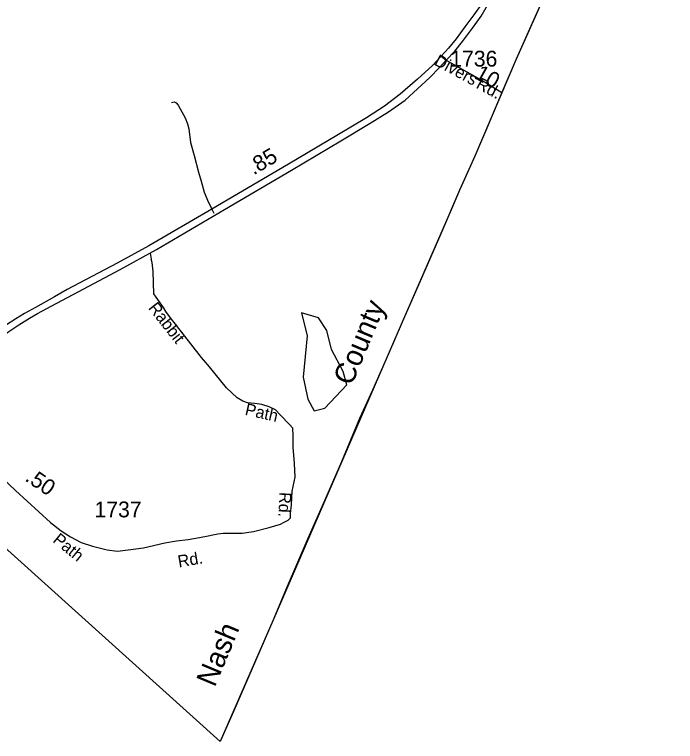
# Model space of a CAD drawing. Extents: x 2220236 to 2384410, y 720751 to 894131.
# Drawn here: x 2340787 to 2346007, y 761777 to 767520 of the extents above; entities that cross this region are included whole.
import ezdxf

# ---------------------------------------------------------------- set-up
doc = ezdxf.new("R2010")
doc.units = 0
for name, color, linetype in [('Exist Boundary Political CountyLine', 7, 'Continuous'), ('Exist Boundary Political CountyLine Label', 7, 'Continuous'), ('Exist Hydrographic Pond Under 1500 Sq Ft', 7, 'Continuous'), ('Exist Railroad Mainline', 7, 'Continuous'), ('Exist Road Non-System Type 51', 7, 'Continuous'), ('Exist Road Non-System Type 51 Label', 7, 'Continuous'), ('Exist Road Primary US Divided Attributed', 7, 'Continuous'), ('Exist Road Primary US Mileage Hundredths English Label', 7, 'Continuous'), ('Exist Road Secondary Mileage Hundredths English Label', 7, 'Continuous'), ('Exist Road Secondary Type 20 Attributed', 7, 'Continuous'), ('Exist Road Secondary Type 51 Attributed', 7, 'Continuous'), ('Exist Road Secondary Type 51 Label', 7, 'Continuous'), ('Exist Road Secondary Type 51 Number Label', 7, 'Continuous')]:
    doc.layers.add(name, color=color, linetype=linetype)

msp = doc.modelspace()

# ---------------------------------------------------------------- linework, layer by layer
at = {"layer": 'Exist Boundary Political CountyLine'}
for points in [[(2344994.6, 767717), (2344864.5, 767429.1), (2344748.7, 767168.8), (2344635.7, 766903.7), (2344523.7, 766639.6), (2344422.1, 766401.1), (2344300.6, 766131.3), (2344153.4, 765788.3), (2343991.1, 765414.9), (2343847.7, 765089), (2343739.5, 764840.1), (2343615.1, 764552.2), (2343512.5, 764327.9), (2343369.2, 763986.8), (2343235.3, 763678.1), (2343104.3, 763379.7), (2342940, 763002.5), (2342827, 762729.8), (2342662.8, 762354.6), (2342515.6, 762013.5), (2342412.1, 761776.9)], [(2342412.1, 761776.9), (2339905.1, 764034.3), (2333719, 766093.2), (2333476.1, 765987.5), (2333096.9, 765807.6)]]:
    msp.add_lwpolyline(points, dxfattribs=at)
at = {"layer": 'Exist Hydrographic Pond Under 1500 Sq Ft'}
msp.add_lwpolyline([(2343154.3, 764389.5), (2343237.4, 764409.3), (2343410.4, 764593.6), (2343383.4, 764700.8), (2343290.5, 764874.2), (2343254.4, 765023.8), (2343187.3, 765122.7), (2343053.4, 765163.2), (2343097.3, 764981.2), (2343067.4, 764655.1), (2343103.5, 764482.6), (2343154.3, 764389.5)], dxfattribs=at)
at = {"layer": 'Exist Railroad Mainline'}
msp.add_lwpolyline([(2344994.6, 767717), (2344873.7, 767449.4), (2344869.4, 767439.8), (2344860.6, 767420.2), (2344839.5, 767372.8), (2344748.7, 767168.8), (2344422.1, 766401.1), (2344316.5, 766166.7), (2344300.6, 766131.3), (2344299.8, 766129.4), (2344299.7, 766129.1), (2344299.3, 766128.2), (2344295.1, 766118.5), (2344234.1, 765976.1), (2343847.7, 765089), (2342827, 762729.8), (2342412.1, 761776.9)], dxfattribs=at)
at = {"layer": 'Exist Road Non-System Type 51'}
for p, q in [((2342311.2, 766053.2), (2342340.6, 765992)), ((2342340.6, 765992), (2342360.2, 765951.3)), ((2341857.8, 765636.1), (2341865.7, 765586.3))]:
    msp.add_line(p, q, dxfattribs=at)
for points in [[(2342027.2, 766824.8), (2342048.2, 766830), (2342063.9, 766821.3), (2342077.9, 766803.8), (2342093.6, 766774.1), (2342133.8, 766704.1), (2342153, 766656.9), (2342163.5, 766616.7), (2342177.5, 766510.1), (2342205.4, 766405.2), (2342240.4, 766274.1), (2342261.3, 766202.4), (2342284, 766116.8), (2342305, 766066.1), (2342311.2, 766053.2)], [(2341974.3, 763346.6), (2342067.1, 763363.1), (2342156.9, 763373.5), (2342246.7, 763389.2), (2342316.3, 763401.4), (2342353.4, 763408.8), (2342392.4, 763416.2), (2342435, 763421.8), (2342485.1, 763423.6), (2342583.3, 763423.6), (2342674.2, 763434.8), (2342798.4, 763468.2), (2342887.4, 763494.1), (2342917.1, 763509), (2342948.6, 763525.7), (2342965.3, 763544.2), (2342967.2, 763577.6), (2342974.6, 763646.3), (2342980.1, 763753.9), (2343002.4, 763865.2), (2342998.7, 763972.8), (2342987.6, 764100.8), (2342987.6, 764193.6), (2342983.8, 764251.1), (2342957.9, 764280.8), (2342885.6, 764356.9), (2342846.6, 764395.8), (2342798.4, 764421.8), (2342739.1, 764438.5), (2342683.5, 764447.8), (2342627.8, 764451.5), (2342588.9, 764464.5), (2342546.3, 764492.3), (2342461, 764570.2), (2342325.6, 764737.2), (2342262.6, 764811.4), (2342112.4, 765002.5), (2342017.8, 765123.1), (2341982.6, 765175.1), (2341962.8, 765205.1), (2341904.7, 765286.4), (2341888, 765314.3), (2341882.5, 765488.7), (2341873.2, 765561), (2341865.7, 765586.3)]]:
    msp.add_lwpolyline(points, dxfattribs=at)
at = {"layer": 'Exist Road Primary US Divided Attributed'}
for points in [[(2346006.6, 771039.3), (2345804.8, 770603.5), (2345738.1, 770425.9), (2345654.7, 770242.3), (2345541.9, 769970.1), (2345379.9, 769609.5), (2345178.7, 769147.1), (2345013.3, 768758.9), (2344836.9, 768349.7), (2344670.6, 767967.9), (2344617.9, 767857.7), (2344574.7, 767777.6), (2344518.8, 767672.1), (2344474.7, 767602.8), (2344414.8, 767517.4), (2344343.9, 767422.1), (2344274.2, 767328.6), (2344213.4, 767255.1), (2344157, 767192)], [(2344196.9, 767158.8), (2344264.3, 767230.8), (2344324.1, 767306), (2344404.8, 767413.3), (2344471.2, 767506.3), (2344511.8, 767577.1), (2344557.8, 767649.4), (2344614.5, 767756.4), (2344658.1, 767837.2), (2344711.6, 767949.1), (2344878.3, 768331.8), (2345060.7, 768746.8), (2345221.6, 769110.3), (2345417.4, 769570.1), (2345491.6, 769737), (2345625.4, 770035.3), (2345780.1, 770409.4), (2345846.9, 770587.4), (2346006.6, 771039.3)], [(2344157, 767192), (2344087.4, 767116.8), (2343970.1, 767010), (2343832.4, 766892.1), (2343709.6, 766795.9), (2343565.3, 766702.9), (2343346.3, 766573.4), (2342949.7, 766337.7), (2342343.9, 765981.9), (2341847.5, 765691.8), (2341598.6, 765555.5), (2341201.7, 765348.9), (2341102.8, 765290.4), (2340951.8, 765205.7), (2340865.5, 765157.6), (2340795.7, 765116.1), (2340715.7, 765062.8), (2340622.5, 764996.1), (2340546.3, 764939), (2340451.2, 764859), (2340376.9, 764798.1), (2340358.2, 764782.9)], [(2340378.7, 764735), (2340403.6, 764756.2), (2340479.7, 764819), (2340573, 764893.3), (2340651, 764950.4), (2340734.8, 765011.4), (2340820.4, 765068.5), (2340906.1, 765121.8), (2340967, 765158), (2341076.3, 765217.3), (2341248.8, 765308.6), (2341620.8, 765506.1), (2341907.8, 765663.8), (2342445.4, 765979.2), (2342974.6, 766291.3), (2343362.9, 766522), (2343595.1, 766661.4), (2343741.1, 766752.7), (2343872.2, 766842.4), (2344066.3, 767021.6), (2344143.8, 767101.3), (2344196.9, 767158.8)]]:
    msp.add_lwpolyline(points, dxfattribs=at)
at = {"layer": 'Exist Road Secondary Type 20 Attributed'}
msp.add_lwpolyline([(2340378.7, 764735), (2340384.7, 764713.4), (2340383.4, 764688.5), (2340378.8, 764663.6), (2340377.4, 764660.3), (2340365.2, 764633), (2340203.6, 764447.8), (2340174.9, 764409.9), (2340166.9, 764387), (2340168, 764364), (2340174.9, 764344.5), (2340210.5, 764304.3), (2340537.1, 764003.3), (2340793.3, 763760.8), (2341071.6, 763507), (2341156.3, 763442.1), (2341228.9, 763393), (2341313.3, 763348.7), (2341402.7, 763319.5), (2341517.9, 763290.2), (2341600.5, 763281.6), (2341684.7, 763290.2), (2341805.1, 763307.5), (2341974.3, 763346.6)], dxfattribs=at)
at = {"layer": 'Exist Road Secondary Type 51 Attributed'}
for points in [[(2344157, 767192), (2344196.9, 767158.8)], [(2344196.9, 767158.8), (2344256, 767124.7), (2344502.5, 766985.4), (2344636.3, 766905)]]:
    msp.add_lwpolyline(points, dxfattribs=at)

# ---------------------------------------------------------------- texts
at = {"layer": 'Exist Boundary Political CountyLine Label'}
for s, p in [('County', (2343448.9, 764580.4)), ('Nash', (2342368.3, 762199.5))]:
    msp.add_text(s, height=164.04, rotation=67.26648, dxfattribs=at).set_placement(p)
at = {"layer": 'Exist Road Non-System Type 51 Label'}
for s, rotation, p in [('Rabbit', 308.03935, (2341838.4, 765200.8)), ('Path', 347.18303, (2342601, 764358.6)), ('Rd.', 267.38231, (2342879, 763748.6))]:
    msp.add_text(s, height=95, rotation=rotation, dxfattribs=at).set_placement(p)
at = {"layer": 'Exist Road Primary US Mileage Hundredths English Label'}
msp.add_text('.85', height=125, rotation=30.43226, dxfattribs=at).set_placement((2342675, 766248.8))
at = {"layer": 'Exist Road Secondary Mileage Hundredths English Label'}
for s, rotation, p in [('.10', 330.53605, (2344371.6, 767043.7)), ('.50', 325.92981, (2340862, 763841.6))]:
    msp.add_text(s, height=125, rotation=rotation, dxfattribs=at).set_placement(p)
at = {"layer": 'Exist Road Secondary Type 51 Label'}
for s, rotation, p in [('Divers', 331.57146, (2344093.6, 767127.1)), ('Rd.', 331.57146, (2344424.5, 766943.5)), ('Path', 320.86085, (2341082.4, 763357.3)), ('Rd.', 9.70858, (2342084.6, 763151.2))]:
    msp.add_text(s, height=95, rotation=rotation, dxfattribs=at).set_placement(p)
at = {"layer": 'Exist Road Secondary Type 51 Number Label'}
for s, p in [('1736', (2344228.2, 767109)), ('1737', (2341418.3, 763547.7))]:
    msp.add_text(s, height=125, dxfattribs=at).set_placement(p)

doc.saveas('drawing.dxf')
